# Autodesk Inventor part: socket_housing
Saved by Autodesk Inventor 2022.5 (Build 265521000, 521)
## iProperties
Created: 2024-12
Part Number: socket_housing
Material: Generic
Document SubType Name: Modeling
Designer: AdminForWorker
Density: 1 g/cm^3
Appearance: Default
Title: socket_housing
Author: AdminForWorker
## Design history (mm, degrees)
feature "Body1"
body "Solid1"
